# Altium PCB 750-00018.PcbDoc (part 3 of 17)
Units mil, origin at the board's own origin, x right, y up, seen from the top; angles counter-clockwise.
Board outline 7086.64 x 6299.21 mil, 8 copper layers (Top Layer, L2, L3, L4, L5, L6, L7, Bottom Layer), stack 60.6 mil thick; 1356 components, 1054 nets, 4851 pads, 4296 vias.
Unrouted connection lines stored in the file: 12.
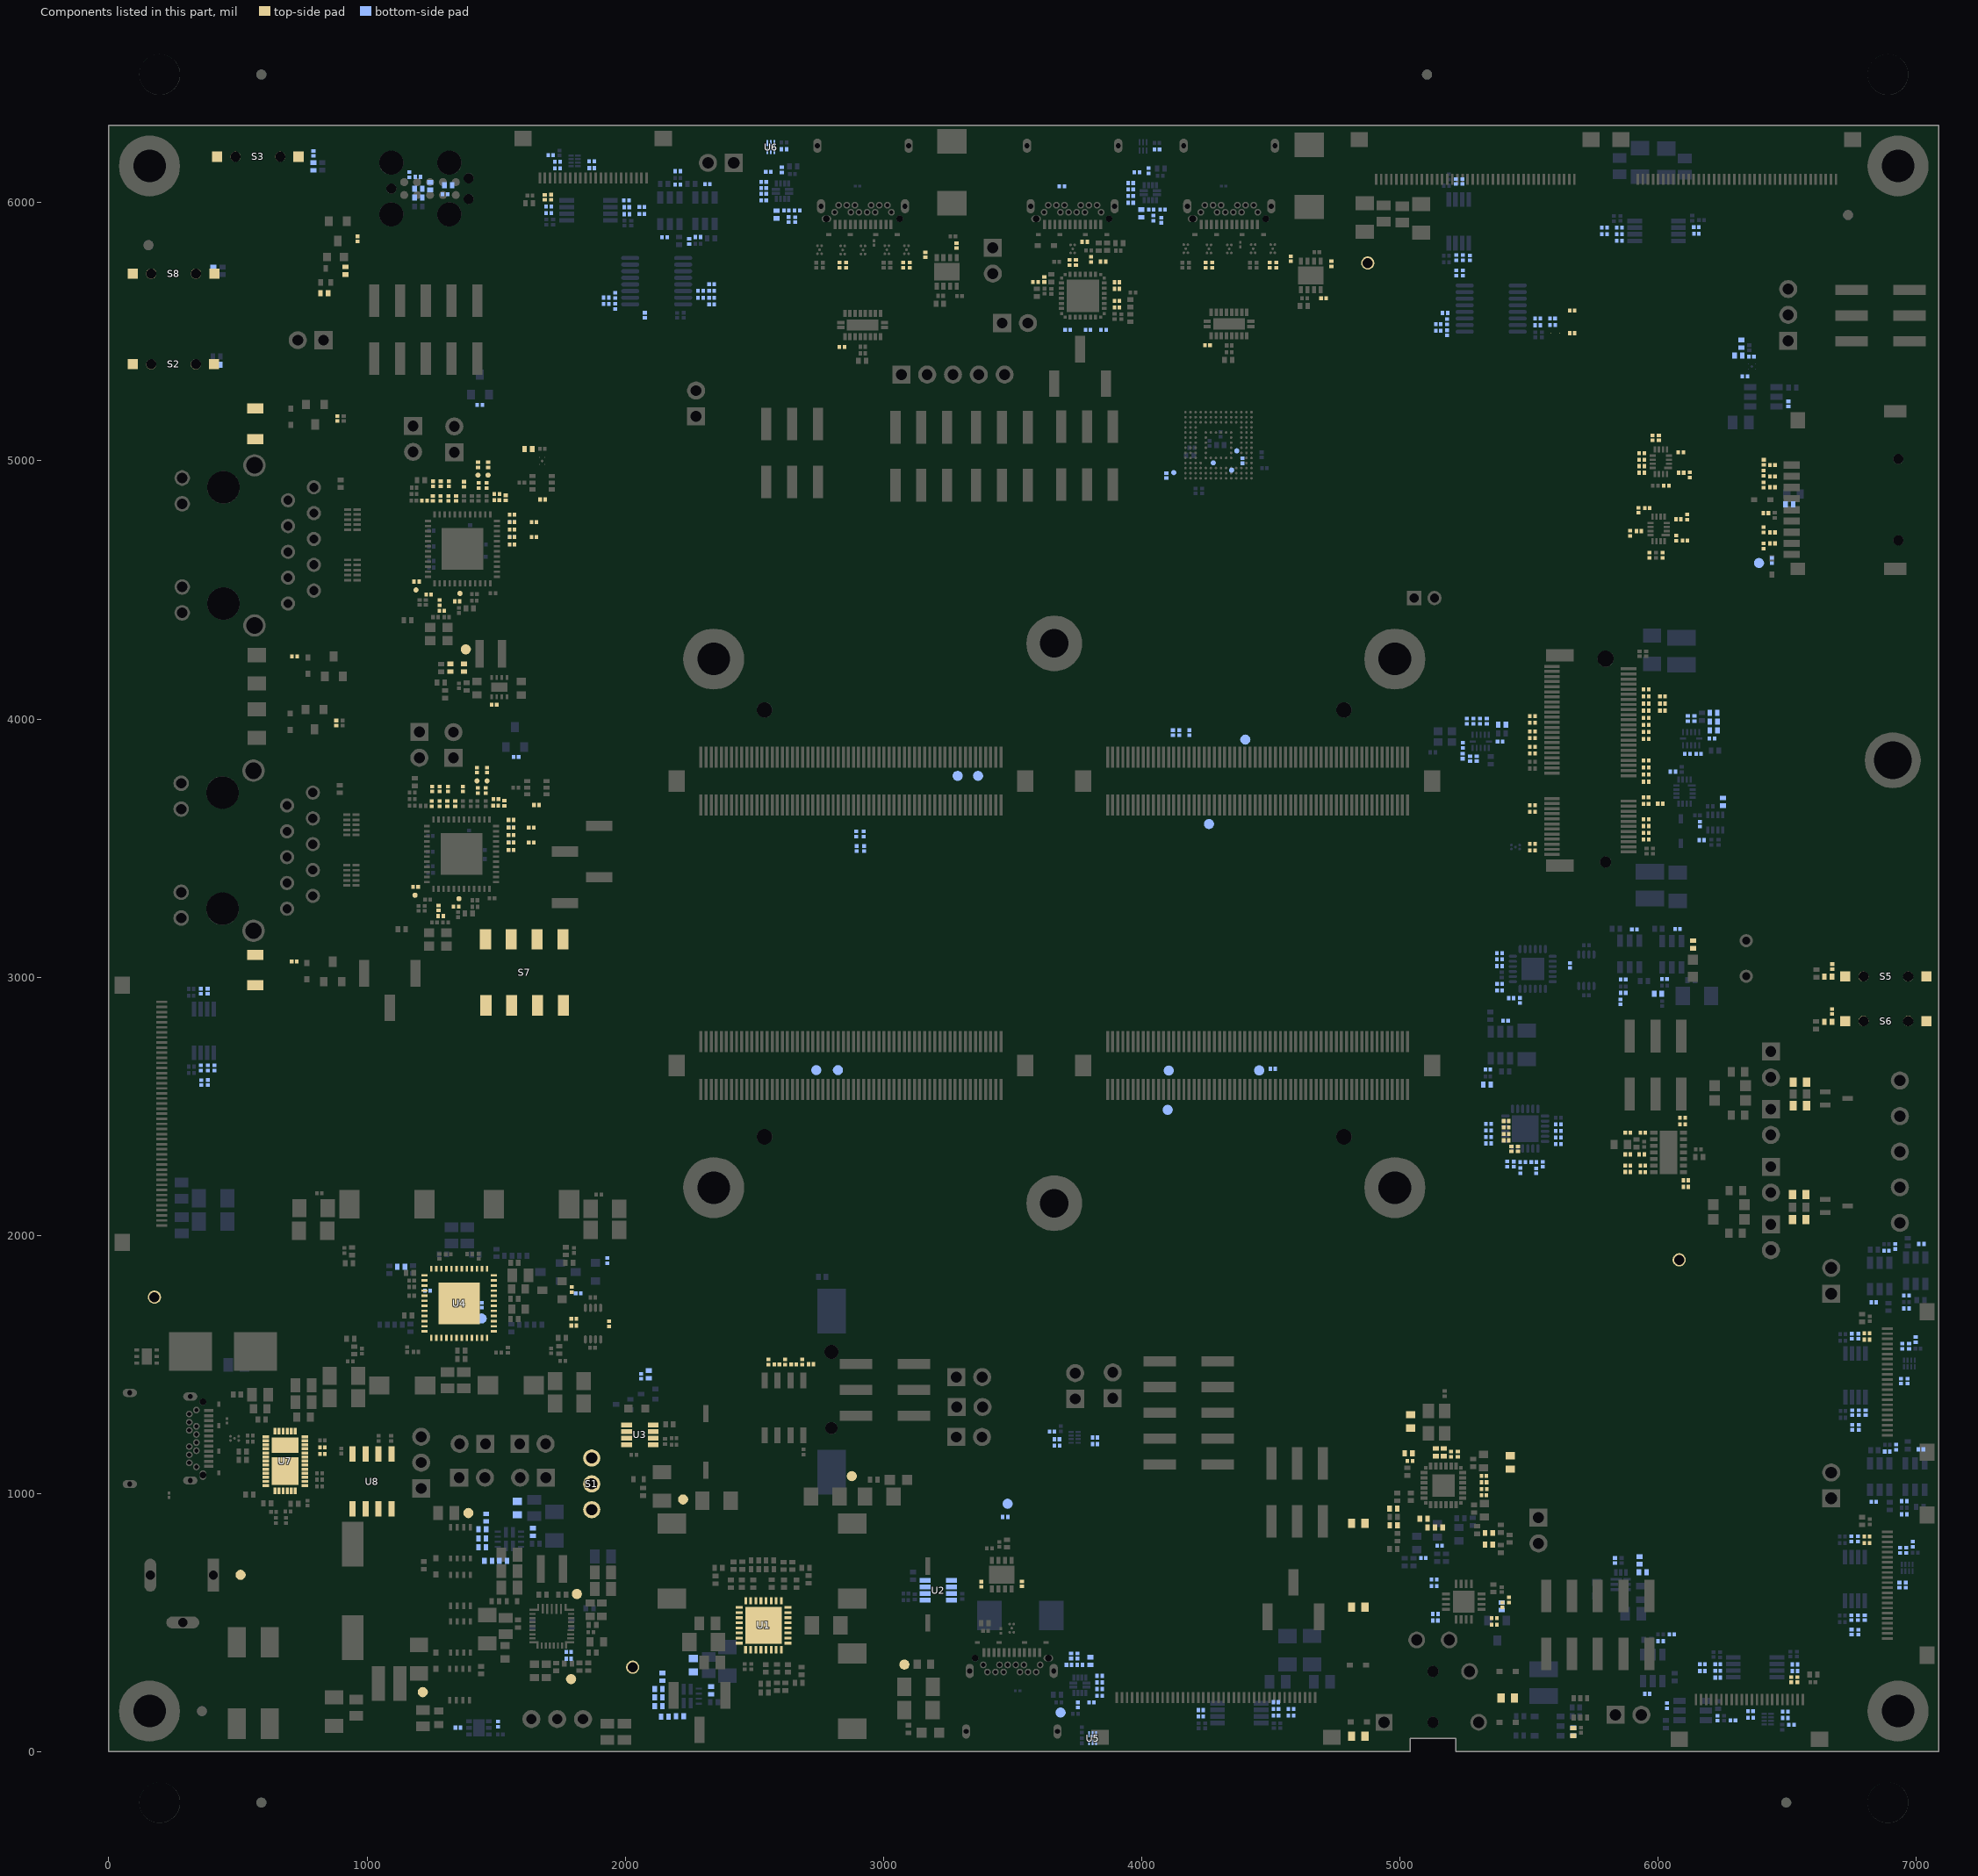
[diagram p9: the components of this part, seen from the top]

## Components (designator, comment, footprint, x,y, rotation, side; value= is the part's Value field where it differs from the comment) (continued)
R78 "0201, 2.2K, 5%" "RES, R0201, Height 0.23mm" 1345.13,3273.14 r0 top value=2.2k
R79 "0201, 2.2K, 5%" "RES, R0201, Height 0.23mm" 1341.29,3671.92 r90 top value=2.2k
R80 "0201, 27 Ohm" "RES, R0201, Height 0.23mm" 1498.34,3664.85 r180 top value=27
R81 "0201, 100 Ohm, 1%" "RES, R0201, Height 0.23mm" 880.75,3984.42 r270 top value=100
R82 "1206, 1M, 5%" "RES, 1206, Height 0.70mm" 567.06,3027.52 r270 top value=1M
R83 "0201, 27 Ohm" "RES, R0201, Height 0.23mm" 1557.78,3492.99 r180 top value=27
R84 "0201, 27 Ohm" "RES, R0201, Height 0.23mm" 1557.78,3521.96 r180 top value=27
R85 "0201, 100 Ohm, 1%" "RES, R0201, Height 0.23mm" 717.9,3061.03 r180 top value=100
R86 "0201, 27 Ohm" "RES, R0201, Height 0.23mm" 1557.78,3550.93 r180 top value=27
R87 "0201, 0 Ohm" "RES, R0201, Height 0.23mm" 1371.42,3728.74 r90 top value=0
R88 "0201, 27 Ohm" "RES, R0201, Height 0.23mm" 1557.78,3579.89 r180 top value=27
R89 "0201, 27 Ohm" "RES, R0201, Height 0.23mm" 1557.78,3608.86 r180 top value=27
R90 "0201, 11k, 1%" "RES, R0201, Height 0.23mm" 1187.88,3349.91 r180 top value=11k
R91 "0201, 0 Ohm" "RES, R0201, Height 0.23mm" 1276.99,3268.29 r270 top value=0
R92 "0201, 1M, 1%" "RES, R0201, Height 0.23mm" 1285.5,3236.84 r0 top value=1M
R93 "0201, 6.04k, 1%" "RES, R0201, Height 0.23mm" 1251.7,3728.74 r270 top value=6.04k
R94 "0201, 11k, 1%" "RES, R0201, Height 0.23mm" 1281.53,3728.74 r270 top value=11k
R95 "0201, 6.04k, 1%" "RES, R0201, Height 0.23mm" 1313.17,3728.74 r270 top value=6.04k
R96 "0201, 6.04k, 1%" "RES, R0201, Height 0.23mm" 1636.09,3579.89 r180 top value=6.04k
R97 "0201, 2.49K, 1%" "RES, R0201, Height 0.23mm" 1636.09,3521.96 r0 top value=2.49k
R98 "0201, 6.04k, 1%" "RES, R0201, Height 0.23mm" 1425.9,3802.07 r270 top value=6.04k
R99 "0201, 6.04k, 1%" "RES, R0201, Height 0.23mm" 1464.72,3802.07 r270 top value=6.04k
R100 "0201, 6.04k, 1%" "RES, R0201, Height 0.23mm" 1498.91,3689.35 r0 top value=6.04k
R101 "0201, 2.49K, 1%" "RES, R0201, Height 0.23mm" 1531.89,3673.64 r90 top value=2.49k
R102 "0201, 2.49K, 1%" "RES, R0201, Height 0.23mm" 1459.11,3722.63 r270 top value=2.49k
R103 "0201, 2.49K, 1%" "RES, R0201, Height 0.23mm" 1428.59,3722.8 r270 top value=2.49k
R104 "0201, 2.49K, 1%" "RES, R0201, Height 0.23mm" 1557.78,3521.96 r180 bottom value=2.49k
R105 "0201, 2.49K, 1%" "RES, R0201, Height 0.23mm" 1557.78,3579.89 r180 bottom value=2.49k
R106 "0201, 2.49K, 1%" "RES, R0201, Height 0.23mm" 1310.75,3671.99 r90 top value=2.49k
R107 "0201, 2.49K, 1%" "RES, R0201, Height 0.23mm" 1280.84,3671.99 r90 top value=2.49k
R108 "0201, 2.49K, 1%" "RES, R0201, Height 0.23mm" 1250.74,3671.99 r90 top value=2.49k
R109 "0201, 0 Ohm" "RES, R0201, Height 0.23mm" 1238.63,4482.59 r0 top value=0
R110 "0201, 0 Ohm" "RES, R0201, Height 0.23mm" 1222.46,4845.96 r0 top value=0
R111 "0201, 2.2K, 5%" "RES, R0201, Height 0.23mm" 1349.07,4455.46 r0 top value=2.2k
R112 "0201, 2.2K, 5%" "RES, R0201, Height 0.23mm" 1344.76,4854.47 r90 top value=2.2k
R113 "0201, 27 Ohm" "RES, R0201, Height 0.23mm" 1502.28,4847.17 r180 top value=27
R114 "0201, 100 Ohm, 1%" "RES, R0201, Height 0.23mm" 884.69,5163.92 r270 top value=100
R115 "1206, 1M, 5%" "RES, 1206, Height 0.70mm" 567.06,5143.47 r90 top value=1M
R116 "0201, 27 Ohm" "RES, R0201, Height 0.23mm" 1561.72,4675.31 r180 top value=27
R117 "0201, 27 Ohm" "RES, R0201, Height 0.23mm" 1561.72,4704.27 r180 top value=27
R118 "0201, 100 Ohm, 1%" "RES, R0201, Height 0.23mm" 718.94,4242.61 r180 top value=100
R119 "0201, 27 Ohm" "RES, R0201, Height 0.23mm" 1561.72,4733.24 r180 top value=27
R120 "0201, 0 Ohm" "RES, R0201, Height 0.23mm" 1375.56,4909.05 r90 top value=0
R121 "0201, 27 Ohm" "RES, R0201, Height 0.23mm" 1561.72,4762.21 r180 top value=27
R122 "0201, 27 Ohm" "RES, R0201, Height 0.23mm" 1561.72,4791.18 r180 top value=27
R123 "0201, 11k, 1%" "RES, R0201, Height 0.23mm" 1191.83,4532.22 r180 top value=11k
R124 "0201, 0 Ohm" "RES, R0201, Height 0.23mm" 1280.93,4450.61 r270 top value=0
R125 "0201, 1M, 1%" "RES, R0201, Height 0.23mm" 1289.44,4419.16 r0 top value=1M
R126 "0201, 6.04k, 1%" "RES, R0201, Height 0.23mm" 1255.64,4910.93 r270 top value=6.04k
R127 "0201, 11k, 1%" "RES, R0201, Height 0.23mm" 1285.47,4910.93 r270 top value=11k
R128 "0201, 6.04k, 1%" "RES, R0201, Height 0.23mm" 1316.62,4910.93 r270 top value=6.04k
R129 "0201, 6.04k, 1%" "RES, R0201, Height 0.23mm" 1646.32,4762.21 r180 top value=6.04k
R130 "0201, 11k, 1%" "RES, R0201, Height 0.23mm" 1646.32,4705.15 r180 top value=11k
R131 "0201, 6.04k, 1%" "RES, R0201, Height 0.23mm" 1429.85,4984.39 r270 top value=6.04k
R132 "0201, 6.04k, 1%" "RES, R0201, Height 0.23mm" 1468.66,4984.39 r270 top value=6.04k
R133 "0201, 6.04k, 1%" "RES, R0201, Height 0.23mm" 1502.85,4871.67 r0 top value=6.04k
R134 "0201, 2.49K, 1%" "RES, R0201, Height 0.23mm" 1536.93,4856.33 r90 top value=2.49k
R135 "0201, 2.49K, 1%" "RES, R0201, Height 0.23mm" 1463.05,4904.7 r270 top value=2.49k
R136 "0201, 2.49K, 1%" "RES, R0201, Height 0.23mm" 1432.53,4904.87 r270 top value=2.49k
R137 "0201, 2.49K, 1%" "RES, R0201, Height 0.23mm" 1561.72,4704.27 r180 bottom value=2.49k
R138 "0201, 2.49K, 1%" "RES, R0201, Height 0.23mm" 1561.72,4762.21 r180 bottom value=2.49k
R139 "0201, 2.49K, 1%" "RES, R0201, Height 0.23mm" 1314.7,4854.3 r90 top value=2.49k
R140 "0201, 2.49K, 1%" "RES, R0201, Height 0.23mm" 1284.79,4854.3 r90 top value=2.49k
R141 "0201, 2.49K, 1%" "RES, R0201, Height 0.23mm" 1254.68,4854.3 r90 top value=2.49k
R142 "0201, 100k, 5%" "RES, R0201, Height 0.23mm" 3536.21,650.36 r90 top value=100k
R143 "0201, 10k, 5%" "RES, R0201, Height 0.23mm" 1444.01,1729.74 r90 bottom value=10k
R144 "0402, 0 Ohm" "RES, R0402, RF" 5091.73,902.15 r0 top value=0
R145 "0201, 0 Ohm" "RES, R0201, Height 0.23mm" 2614.54,6206.95 r180 bottom value=0
R146 "0201, 0 Ohm" "RES, R0201, Height 0.23mm" 4059.28,6205.78 r180 bottom value=0
R147 "0201, 1.0k, 5%" "RES, R0201, Height 0.23mm" 2633,5934.14 r270 bottom value=1.0k
R148 "0402, 909k, 1%" "RES, R0402, RF" 2585.9,5953.71 r270 bottom value=909k
R149 "0201, 47k, 1%" "RES, R0201, Height 0.23mm" 1817.86,1775.2 r0 bottom value=47k
R150 "0201, 200k, 1%" "RES, R0201, Height 0.23mm" 2536,6008.77 r180 bottom value=200k
R151 "0201, 200k, 1%" "RES, R0201, Height 0.23mm" 2553.91,6118.73 r180 bottom value=200k
R152 "0201, 10k, 5%" "RES, R0201, Height 0.23mm" 2623.88,5969.02 r0 bottom value=10k
R153 "0201, 200k, 1%" "RES, R0201, Height 0.23mm" 2536,6033.9 r180 bottom value=200k
R154 "0201, 200k, 1%" "RES, R0201, Height 0.23mm" 2536,6080.37 r180 bottom value=200k
R155 "0201, 1.0k, 5%" "RES, R0201, Height 0.23mm" 2665.88,5969.08 r180 bottom value=1.0k
R156 "0201, 1.0k, 5%" "RES, R0201, Height 0.23mm" 2536,6056.5 r0 bottom value=1.0k
R157 "0201, 10k, 5%" "RES, R0201, Height 0.23mm" 2605.96,6127.17 r90 bottom value=10k
R158 "0201, 100k, 5%" "RES, R0201, Height 0.23mm" 3162.21,5797.67 r90 top value=100k
R159 "0201, 10k, 5%" "RES, R0201, Height 0.23mm" 2839.47,5441.38 r0 top value=10k
R160 "0201, 10k, 5%" "RES, R0201, Height 0.23mm" 6016.99,4087.9 r180 top value=10k
R161 "0201, 10k, 5%" "RES, R0201, Height 0.23mm" 1930.77,1902.17 r270 bottom value=10k
R162 "0201, 1.0k, 5%" "RES, R0201, Height 0.23mm" 4045.78,5939.69 r270 bottom value=1.0k
R163 "0402, 909k, 1%" "RES, R0402, RF" 3999.01,5957.89 r270 bottom value=909k
R164 "0201, 10k, 5%" "RES, R0201, Height 0.23mm" 4075.93,5931.94 r270 bottom value=10k
R165 "0201, 200k, 1%" "RES, R0201, Height 0.23mm" 3957.18,5999.37 r180 bottom value=200k
R166 "0201, 200k, 1%" "RES, R0201, Height 0.23mm" 3981.83,6117.74 r180 bottom value=200k
R167 "0201, 10k, 5%" "RES, R0201, Height 0.23mm" 4036.83,5973.55 r0 bottom value=10k
R168 "0201, 200k, 1%" "RES, R0201, Height 0.23mm" 3957.18,6025.38 r180 bottom value=200k
R169 "0201, 200k, 1%" "RES, R0201, Height 0.23mm" 3957.19,6075.99 r180 bottom value=200k
R170 "0201, 1.0k, 5%" "RES, R0201, Height 0.23mm" 4080.78,5973.24 r180 bottom value=1.0k
R171 "0201, 1.0k, 5%" "RES, R0201, Height 0.23mm" 3957.19,6050.85 r0 bottom value=1.0k
R172 "0201, 10k, 5%" "RES, R0201, Height 0.23mm" 4026.16,6123.19 r90 bottom value=10k
R173 "0201, 100k, 5%" "RES, R0201, Height 0.23mm" 4576.9,5782.77 r90 top value=100k
R174 "0201, 10k, 5%" "RES, R0201, Height 0.23mm" 4254.62,5448.08 r0 top value=10k
R175 "0201, 10k, 5%" "RES, R0201, Height 0.23mm" 4704.5,5630.07 r180 top value=10k
R176 "0402, 0 Ohm" "RES, R0402, RF" 417.35,5371.37 r180 bottom value=0
R177 "0603, 0 Ohm" "RES, R0603, RF" 5417.44,207.97 r180 top value=0
R178 "0603, 0 Ohm" "RES, R0603, RF" 4838.42,559.47 r0 top value=0
R179 "0603, 0 Ohm" "RES, R0603, RF" 5427.17,1120.59 r270 top value=0
R180 "0603, 0 Ohm" "RES, R0603, RF" 4839.09,884.98 r0 top value=0
R181 "0603, 0 Ohm" "RES, R0603, RF" 5041.54,1279.36 r270 top value=0
R182 "0603, 0 Ohm" "RES, R0603, RF" 4839,60.01 r0 top value=0
R183 "0201, 27 Ohm" "RES, R0201, Height 0.23mm" 5326.01,1017.94 r180 top value=27
R184 "0201, 27 Ohm" "RES, R0201, Height 0.23mm" 5325.61,993.06 r180 top value=27
R185 "0201, 27 Ohm" "RES, R0201, Height 0.23mm" 5325.2,1068.5 r180 top value=27
R186 "0201, 27 Ohm" "RES, R0201, Height 0.23mm" 5325.81,1043.83 r180 top value=27
R187 "0201, 10k, 5%" "RES, R0201, Height 0.23mm" 5153.82,797.72 r0 bottom value=10k
R188 "0402, 330k, 1%" "RES, R0402, RF" 5393.56,563.42 r90 bottom value=330k
R189 "0201, 0 Ohm" "RES, R0201, Height 0.23mm" 5198.09,1152.54 r270 top value=0
R190 "0201, 0 Ohm" "RES, R0201, Height 0.23mm" 5224,1152.24 r270 top value=0
R191 "0201, 10k, 5%" "RES, R0201, Height 0.23mm" 5091,750.96 r180 bottom value=10k
R192 "0201, 0 Ohm" "RES, R0201, Height 0.23mm" 5132.44,641.5 r0 bottom value=0
R193 "0402, 68.1k, 1%" "RES, R0402, RF" 1445.97,792.73 r0 bottom value=68.1k
R194 "0201, 0 Ohm" "RES, R0201, Height 0.23mm" 5422.49,588.33 r270 top value=0
R195 "0201, 0 Ohm" "RES, R0201, Height 0.23mm" 5137.15,508.39 r0 bottom value=0
R196 "0201, 4.7k, 5%" "RES, R0201, Height 0.23mm" 5132.22,667.17 r0 bottom value=4.7k
R197 "0201, 4.7k, 5%" "RES, R0201, Height 0.23mm" 5397.35,568.65 r90 top value=4.7k
R198 "0201, 100k, 5%" "RES, R0201, Height 0.23mm" 5137.2,533.64 r0 bottom value=100k
R199 "0402, 4.99k, 1%" "RES, R0402, RF" 1445.97,826.9 r180 bottom value=4.99k
R200 "0402, 68.1k, 1%" "RES, R0402, RF" 2129.04,176.74 r0 bottom value=68.1k
R201 "0201, 0 Ohm" "RES, R0201, Height 0.23mm" 5365.72,492.02 r180 top value=0
R202 "0201, 100k, 5%" "RES, R0201, Height 0.23mm" 5365.71,517.41 r0 top value=100k
R203 "0402, 0 Ohm" "RES, R0402, RF" 5672.06,76.79 r270 top value=0
R204 "0402, 2.2k, 5%" "RES, R0402, RF" 4975.68,876.38 r180 top value=2.2k
R205 "0402, 47k, 1%" "RES, R0402, RF" 4974.94,942.22 r180 top value=47k
R206 "0402, 100k, 1%" "RES, R0402, RF" 5671.34,77.78 r270 bottom value=100k
R207 "0402, 0 Ohm" "RES, R0402, RF" 5344.65,803.14 r0 top value=0
R208 "0402, 0 Ohm" "RES, R0402, RF" 5344.35,847.44 r0 top value=0
R209 "0201, 0 Ohm" "RES, R0201, Height 0.23mm" 5613.69,2404.55 r180 bottom value=0
R210 "0201, 0 Ohm" "RES, R0201, Height 0.23mm" 827.26,1179.45 r0 top value=0
R211 "0201, 2.2K, 5%" "RES, R0201, Height 0.23mm" 4578.47,165.88 r180 bottom value=2.2k
R212 "0201, 2.2K, 5%" "RES, R0201, Height 0.23mm" 4578.47,140.49 r180 bottom value=2.2k
R213 "0201, 2.2K, 5%" "RES, R0201, Height 0.23mm" 5244.31,5727.26 r90 bottom value=2.2k
R214 "0201, 2.2K, 5%" "RES, R0201, Height 0.23mm" 5218.49,5727.26 r90 bottom value=2.2k
R215 "0201, 2.2K, 5%" "RES, R0201, Height 0.23mm" 5792.26,5877.28 r0 bottom value=2.2k
R216 "0201, 2.2K, 5%" "RES, R0201, Height 0.23mm" 5792.39,5903.06 r0 bottom value=2.2k
R217 "0201, 2.2K, 5%" "RES, R0201, Height 0.23mm" 383.39,2591.87 r90 bottom value=2.2k
R218 "0201, 2.2K, 5%" "RES, R0201, Height 0.23mm" 357.58,2591.62 r90 bottom value=2.2k
R219 "0201, 2.2K, 5%" "RES, R0201, Height 0.23mm" 5590.88,5551.51 r180 bottom value=2.2k
R220 "0201, 2.2K, 5%" "RES, R0201, Height 0.23mm" 5591.11,5525.46 r180 bottom value=2.2k
R221 "0201, 10k, 5%" "RES, R0201, Height 0.23mm" 2924.61,3498.16 r270 bottom value=10k
R222 "0402, 0 Ohm" "RES, R0402, RF" 6214.75,3956.24 r0 bottom value=0
R223 "0402, 0 Ohm" "RES, R0402, RF" 6214.84,3990.2 r0 bottom value=0
R224 "0402, 0 Ohm" "RES, R0402, RF" 5395.31,3978.41 r0 bottom value=0
R225 "0402, 0 Ohm" "RES, R0402, RF" 6214.52,4023.88 r0 bottom value=0
R226 "0201, 49.9k, 1%" "RES, R0201, Height 0.23mm" 6156.8,3865.05 r180 bottom value=49.9k
R227 "0201, 49.9k, 1%" "RES, R0201, Height 0.23mm" 6113.43,3865.05 r0 bottom value=49.9k
R228 "0201, 10k, 5%" "RES, R0201, Height 0.23mm" 5387.98,3913 r0 bottom value=10k
R229 "0201, 10k, 5%" "RES, R0201, Height 0.23mm" 6208.37,3924.64 r0 bottom value=10k
R230 "0201, 10k, 5%" "RES, R0201, Height 0.23mm" 1492.29,4055.55 r180 top value=10k
R231 "0402, 66.5k, 1%" "RES, R0402, RF" 1322.8,4198.42 r90 top value=66.5k
R232 "0201, 49.9k, 1%" "RES, R0201, Height 0.23mm" 6162.26,3592.82 r90 bottom value=49.9k
R233 "0402, 10k, 1%" "RES, R0402, RF" 6251.33,3678.99 r270 bottom value=10.0k
R234 "0201, 0 Ohm" "RES, R0201, Height 0.23mm" 5533.72,5551.18 r180 bottom value=0
R235 "0201, 10k, 5%" "RES, R0201, Height 0.23mm" 2895.68,3498.14 r270 bottom value=10k
R236 "0201, 0 Ohm" "RES, R0201, Height 0.23mm" 5953.3,4114.79 r180 top value=0
R237 "0201, 0 Ohm" "RES, R0201, Height 0.23mm" 6075.1,3186.34 r0 bottom value=0
R238 "0201, 0 Ohm" "RES, R0201, Height 0.23mm" 5953.3,4087.27 r180 top value=0
R239 "0402, 2.2k, 5%" "RES, R0402, RF" 6135.05,3126.64 r90 top value=2.2k
R240 "0201, 0 Ohm" "RES, R0201, Height 0.23mm" 5953.3,4059.76 r180 top value=0
R241 "0201, 0 Ohm" "RES, R0201, Height 0.23mm" 5953.3,4032.25 r180 top value=0
R242 "0201, 0 Ohm" "RES, R0201, Height 0.23mm" 5953.3,4004.73 r180 top value=0
R243 "0201, 0 Ohm" "RES, R0201, Height 0.23mm" 5513.08,4010.79 r180 top value=0
R244 "0402, 0 Ohm" "RES, R0402, RF" 5999.5,2936.63 r0 bottom value=0
R245 "0201, 0 Ohm" "RES, R0201, Height 0.23mm" 5953.3,3977.22 r180 top value=0
R246 "0201, 0 Ohm" "RES, R0201, Height 0.23mm" 5513.08,3985.14 r180 top value=0
R247 "0201, 0 Ohm" "RES, R0201, Height 0.23mm" 5953.3,3949.71 r180 top value=0
R248 "0201, 49.9k, 1%" "RES, R0201, Height 0.23mm" 6024.56,2992.64 r180 bottom value=49.9k
R249 "0201, 0 Ohm" "RES, R0201, Height 0.23mm" 5953.3,3922.19 r180 top value=0
R250 "0201, 0 Ohm" "RES, R0201, Height 0.23mm" 5513.08,3951.24 r180 top value=0
R251 "0201, 0 Ohm" "RES, R0201, Height 0.23mm" 5513.08,3925.8 r180 top value=0
R252 "0402, 4.99k, 1%" "RES, R0402, RF" 2128.88,210.43 r180 bottom value=4.99k
R253 "0402, 30k, 1%" "RES, R0402, RF" 1641.59,850.96 r90 bottom value=30k
R254 "0201, 0 Ohm" "RES, R0201, Height 0.23mm" 5953.3,3839.65 r180 top value=0
R255 "0201, 0 Ohm" "RES, R0201, Height 0.23mm" 5533.51,5525.22 r180 bottom value=0
R256 "0201, 1.0k, 5%" "RES, R0201, Height 0.23mm" 5953.3,3812.14 r180 top value=1.0k
R257 "0201, 1.0k, 5%" "RES, R0201, Height 0.23mm" 5953.3,3784.63 r180 top value=1.0k
R258 "0201, 1.0k, 5%" "RES, R0201, Height 0.23mm" 5953.3,3757.11 r180 top value=1.0k
R259 "0201, 10k, 5%" "RES, R0201, Height 0.23mm" 6008.45,3672 r180 top value=10k
R260 "0402, 27.4k, 1%" "RES, R0402, RF" 1527.02,738.76 r180 bottom value=27.4k
R261 "0201, 1.0k, 5%" "RES, R0201, Height 0.23mm" 5953.1,3696.84 r180 top value=1.0k
R262 "0201, 10k, 5%" "RES, R0201, Height 0.23mm" 4507.57,2645.01 r0 bottom value=10k
R263 "0201, 0 Ohm" "RES, R0201, Height 0.23mm" 5513.08,3666.42 r180 top value=0
R264 "0201, 0 Ohm" "RES, R0201, Height 0.23mm" 5953.1,3670.74 r180 top value=0
R265 "0201, 0 Ohm" "RES, R0201, Height 0.23mm" 5953.38,3611.33 r180 top value=0
R266 "0201, 0 Ohm" "RES, R0201, Height 0.23mm" 5953.3,3585.33 r180 top value=0
R267 "0201, 0 Ohm" "RES, R0201, Height 0.23mm" 5953.2,3559.47 r180 top value=0
R268 "0201, 0 Ohm" "RES, R0201, Height 0.23mm" 5953.4,3533.91 r180 top value=0
R269 "0201, 0 Ohm" "RES, R0201, Height 0.23mm" 5513.08,3516.77 r180 top value=0
R270 "0201, 0 Ohm" "RES, R0201, Height 0.23mm" 5513.08,3491.09 r180 top value=0
R271 "0402, 30k, 1%" "RES, R0402, RF" 2331.78,237.37 r90 bottom value=30k
R272 "0402, 27.4k, 1%" "RES, R0402, RF" 2211.7,136.92 r180 bottom value=27.4k
R273 "0201, 0 Ohm" "RES, R0201, Height 0.23mm" 827.26,1153.58 r0 top value=0
R274 "0402, 0 Ohm" "RES, R0402, RF" 5151.06,867.94 r0 top value=0
R275 "0603, 60.4, 1%" "RES, R0603, RF" 6548.73,2593.76 r180 top value=60.4
R276 "0402, 0 Ohm" "RES, R0402, RF" 5121.54,867.94 r180 top value=0
R277 "0603, 60.4, 1%" "RES, R0603, RF" 6548.73,2502.5 r0 top value=60.4
R278 "0201, 0 Ohm" "RES, R0201, Height 0.23mm" 1780.94,386.89 r0 bottom value=0
R279 "0201, 4.7k, 5%" "RES, R0201, Height 0.23mm" 6094.87,2455.67 r180 top value=4.7k
R280 "0201, 0 Ohm" "RES, R0201, Height 0.23mm" 1780.85,360.59 r0 bottom value=0
R281 "0201, 0 Ohm" "RES, R0201, Height 0.23mm" 5513.08,3892.69 r180 top value=0
R282 "0603, 60.4, 1%" "RES, R0603, RF" 6546.49,2158.23 r180 top value=60.4
R283 "0201, 0 Ohm" "RES, R0201, Height 0.23mm" 5513.08,3867.07 r180 top value=0
R284 "0603, 60.4, 1%" "RES, R0603, RF" 6546.49,2060.58 r0 top value=60.4
R285 "0201, 200k, 1%" "RES, R0201, Height 0.23mm" 6986.66,804.03 r90 bottom value=200k
R286 "0201, 4.7k, 5%" "RES, R0201, Height 0.23mm" 6107.37,2187.79 r180 top value=4.7k
R287 "0201, 10k, 5%" "RES, R0201, Height 0.23mm" 3713.48,5506.89 r180 bottom value=10k
R288 "0201, 4.7k, 5%" "RES, R0201, Height 0.23mm" 3588.51,5692.93 r0 top value=4.7k
R289 "0201, 4.7k, 5%" "RES, R0201, Height 0.23mm" 6016.99,4059.62 r180 top value=4.7k
R290 "0201, 4.7k, 5%" "RES, R0201, Height 0.23mm" 3904.18,5691.39 r180 top value=4.7k
R291 "0201, 10k, 5%" "RES, R0201, Height 0.23mm" 3622.71,5702.23 r90 top value=10k
R292 "0201, 10k, 5%" "RES, R0201, Height 0.23mm" 3850.77,5771.36 r0 top value=10k
R293 "0201, 4.7k, 5%" "RES, R0201, Height 0.23mm" 3904.18,5665.95 r180 top value=4.7k
R294 "0201, 4.7k, 5%" "RES, R0201, Height 0.23mm" 3904.21,5619.25 r180 top value=4.7k
R295 "0201, 10k, 5%" "RES, R0201, Height 0.23mm" 3803.97,5780.06 r90 top value=10k
R296 "0201, 1.0k, 5%" "RES, R0201, Height 0.23mm" 3904.21,5593.77 r0 top value=1.0k
R297 "0201, 1.0k, 5%" "RES, R0201, Height 0.23mm" 3792.16,5506.89 r180 bottom value=1.0k
R298 "0201, 0 Ohm" "RES, R0201, Height 0.23mm" 3852.35,5506.89 r180 bottom value=0
R299 "0201, 4.7k, 5%" "RES, R0201, Height 0.23mm" 6016.99,4032.19 r180 top value=4.7k
R300 "0201, 0 Ohm" "RES, R0201, Height 0.23mm" 5297.42,3846.08 r90 bottom value=0
R301 "0402, 100k, 1%" "RES, R0402, RF" 1375.56,4198.42 r90 top value=100k
R302 "0201, 0 Ohm" "RES, R0201, Height 0.23mm" 5613.69,2429.99 r180 bottom value=0
R303 "0201, 10k, 5%" "RES, R0201, Height 0.23mm" 5553.28,2275.19 r270 bottom value=10k
R304 "0201, 0 Ohm" "RES, R0201, Height 0.23mm" 6440.88,4614.13 r90 bottom value=0
R305 "0201, 0 Ohm" "RES, R0201, Height 0.23mm" 6017.19,4633.99 r90 top value=0
R306 "0201, 0 Ohm" "RES, R0201, Height 0.23mm" 6070.24,4700.85 r270 top value=0
R307 "0201, 0 Ohm" "RES, R0201, Height 0.23mm" 6078.7,4773.74 r0 top value=0
R308 "0201, 0 Ohm" "RES, R0201, Height 0.23mm" 5957.64,4817.39 r180 top value=0
R309 "0201, 0 Ohm" "RES, R0201, Height 0.23mm" 6442.61,4897.47 r0 top value=0
R310 "0201, 0 Ohm" "RES, R0201, Height 0.23mm" 5925.37,4727.64 r180 top value=0
R311 "0201, 0 Ohm" "RES, R0201, Height 0.23mm" 6417.24,4797.49 r0 top value=0
R312 "0201, 0 Ohm" "RES, R0201, Height 0.23mm" 6089.06,4953.85 r0 top value=0
R313 "0201, 0 Ohm" "RES, R0201, Height 0.23mm" 6442.61,4722.86 r0 top value=0
R314 "0201, 0 Ohm" "RES, R0201, Height 0.23mm" 6088,5032.9 r0 top value=0
R315 "0201, 0 Ohm" "RES, R0201, Height 0.23mm" 6442.61,4679.99 r0 top value=0
R316 "0201, 0 Ohm" "RES, R0201, Height 0.23mm" 6442.8,4983.49 r0 top value=0
R317 "0201, 0 Ohm" "RES, R0201, Height 0.23mm" 6442.61,4939.89 r0 top value=0
R318 "0402, 0 Ohm" "RES, R0402, RF" 6508.01,4831.19 r180 bottom value=0
R319 "0201, 0 Ohm" "RES, R0201, Height 0.23mm" 6504.35,5220.13 r270 bottom value=0
R320 "0402, 10k, 1%" "RES, R0402, RF" 1198.8,6019.29 r0 bottom value=10.0k
R321 "0402, 10k, 1%" "RES, R0402, RF" 1198.8,6053.95 r0 bottom value=10.0k
R322 "0201, 49.9k, 1%" "RES, R0201, Height 0.23mm" 1197.16,6099.9 r180 bottom value=49.9k
R323 "0402, 10k, 1%" "RES, R0402, RF" 1243.79,6063.88 r90 bottom value=10.0k
R324 "0402, 10k, 1%" "RES, R0402, RF" 1314.58,6067.47 r180 bottom value=10.0k
R325 "0201, 0 Ohm" "RES, R0201, Height 0.23mm" 3720.05,5768 r270 top value=0
R326 "0201, 174k, 1%" "RES, R0201, Height 0.23mm" 3378.5,648.92 r270 top value=174k
R327 "0201, 10k, 5%" "RES, R0201, Height 0.23mm" 2658.41,5933.97 r270 bottom value=10k
R328 "0201, 0 Ohm" "RES, R0201, Height 0.23mm" 5386.13,2973.64 r0 bottom value=0
R329 "0201, 0 Ohm" "RES, R0201, Height 0.23mm" 5386.13,2948.6 r0 bottom value=0
R330 "0201, 10k, 5%" "RES, R0201, Height 0.23mm" 5386.09,3043.24 r180 bottom value=10k
R331 "0201, 10k, 5%" "RES, R0201, Height 0.23mm" 1656.32,3666.72 r180 top value=10k
R332 "0201, 0 Ohm" "RES, R0201, Height 0.23mm" 5386.09,3069.74 r180 bottom value=0
R333 "0201, 0 Ohm" "RES, R0201, Height 0.23mm" 5464.78,2909.9 r270 bottom value=0
R334 "0201, 0 Ohm" "RES, R0201, Height 0.23mm" 5430.96,2918.88 r0 bottom value=0
R335 "0201, 0 Ohm" "RES, R0201, Height 0.23mm" 5386.09,3093.58 r0 bottom value=0
R336 "0201, 0 Ohm" "RES, R0201, Height 0.23mm" 3076.28,5757.57 r90 top value=0
R337 "0201, 0 Ohm" "RES, R0201, Height 0.23mm" 3101.84,5757.57 r90 top value=0
R338 "0201, 100k, 1%" "RES, R0201, Height 0.23mm" 3283.04,5833.81 r270 top value=100k
R339 "0201, 0 Ohm" "RES, R0201, Height 0.23mm" 2829.95,5757.57 r270 top value=0
R340 "0201, 0 Ohm" "RES, R0201, Height 0.23mm" 2855.1,5757.57 r270 top value=0
R341 "0201, 0 Ohm" "RES, R0201, Height 0.23mm" 4495.34,5757.57 r90 top value=0
R342 "0201, 0 Ohm" "RES, R0201, Height 0.23mm" 4520.89,5757.57 r90 top value=0
R343 "0201, 100k, 1%" "RES, R0201, Height 0.23mm" 4734.47,5763.35 r90 top value=100k
R344 "0201, 0 Ohm" "RES, R0201, Height 0.23mm" 4247.67,5757.57 r270 top value=0
R345 "0201, 0 Ohm" "RES, R0201, Height 0.23mm" 4273.03,5757.57 r270 top value=0
R346 "0402, 22.1k, 1%" "RES, R0402, RF" 5033.24,1156.55 r180 top value=22.1k
R347 "0201, 4.7k, 5%" "RES, R0201, Height 0.23mm" 5038.75,1126.3 r0 top value=4.7k
R348 "0201, 10k, 5%" "RES, R0201, Height 0.23mm" 5174.98,5572.68 r180 bottom value=10k
R349 "0201, 10k, 5%" "RES, R0201, Height 0.23mm" 4519.41,191.79 r0 bottom value=10k
R350 "0201, 0 Ohm" "RES, R0201, Height 0.23mm" 5908.19,3184.78 r0 bottom value=0
R351 "0201, 0 Ohm" "RES, R0201, Height 0.23mm" 5243.57,3898.13 r270 bottom value=0
R352 "0201, 10k, 5%" "RES, R0201, Height 0.23mm" 6168.61,3531.08 r180 bottom value=10k
R353 "0201, 200k, 1%" "RES, R0201, Height 0.23mm" 1711.31,6183.79 r180 bottom value=200k
R354 "0201, 4.7k, 5%" "RES, R0201, Height 0.23mm" 5882.55,2397.49 r180 top value=4.7k
R355 "0201, 0 Ohm" "RES, R0201, Height 0.23mm" 6094.77,2430.09 r0 top value=0
R356 "0201, 4.7k, 5%" "RES, R0201, Height 0.23mm" 5882.55,2313.8 r180 top value=4.7k
R357 "0201, 0 Ohm" "RES, R0201, Height 0.23mm" 5940.66,2397.48 r180 top value=0
R358 "0201, 0 Ohm" "RES, R0201, Height 0.23mm" 5936.87,2313.8 r180 top value=0
R359 "0201, 10k, 5%" "RES, R0201, Height 0.23mm" 6961.41,780.3 r90 bottom value=10k
R360 "0201, 10k, 5%" "RES, R0201, Height 0.23mm" 6936.52,780.14 r90 bottom value=10k
R361 "0201, 4.7k, 5%" "RES, R0201, Height 0.23mm" 5882.55,2245.76 r0 top value=4.7k
R362 "0201, 0 Ohm" "RES, R0201, Height 0.23mm" 6107.44,2213.3 r0 top value=0
R363 "0201, 4.7k, 5%" "RES, R0201, Height 0.23mm" 5882.55,2270.85 r0 top value=4.7k
R364 "0201, 0 Ohm" "RES, R0201, Height 0.23mm" 5940.66,2270.91 r180 top value=0
R365 "0201, 0 Ohm" "RES, R0201, Height 0.23mm" 5940.66,2245.35 r180 top value=0
R366 "0201, 49.9k, 1%" "RES, R0201, Height 0.23mm" 962.64,5859.42 r270 top value=49.9k
R367 "0201, 0 Ohm" "RES, R0201, Height 0.23mm" 1712.84,6020.91 r90 top value=0
R368 "0201, 0 Ohm" "RES, R0201, Height 0.23mm" 1688.35,6020.7 r90 top value=0
R369 "0201, 0 Ohm" "RES, R0201, Height 0.23mm" 6808.38,808.66 r0 top value=0
R370 "0201, 0 Ohm" "RES, R0201, Height 0.23mm" 6808.38,833.59 r0 top value=0
R371 "0201, 10k, 5%" "RES, R0201, Height 0.23mm" 6959.63,645.34 r270 bottom value=10k
R372 "0201, 10k, 5%" "RES, R0201, Height 0.23mm" 6934.29,645.34 r270 bottom value=10k
R373 "0201, 10k, 5%" "RES, R0201, Height 0.23mm" 1737.13,6157.88 r180 bottom value=10k
R374 "0201, 10k, 5%" "RES, R0201, Height 0.23mm" 1737.13,6132.41 r180 bottom value=10k
R375 "0201, 10k, 5%" "RES, R0201, Height 0.23mm" 1870.37,6159.56 r0 bottom value=10k
R376 "0201, 10k, 5%" "RES, R0201, Height 0.23mm" 1870.67,6133.87 r0 bottom value=10k
R377 "0201, 200k, 1%" "RES, R0201, Height 0.23mm" 6516.1,104.56 r0 bottom value=200k
R378 "0201, 200k, 1%" "RES, R0201, Height 0.23mm" 6997.38,1596 r90 bottom value=200k
R379 "0201, 0 Ohm" "RES, R0201, Height 0.23mm" 6808.84,1596 r0 top value=0
R380 "0201, 0 Ohm" "RES, R0201, Height 0.23mm" 6808.67,1620.58 r0 top value=0
R381 "0201, 0 Ohm" "RES, R0201, Height 0.23mm" 6515.2,279.22 r270 top value=0
R382 "0201, 0 Ohm" "RES, R0201, Height 0.23mm" 6539.01,279.25 r270 top value=0
R383 "0201, 10k, 5%" "RES, R0201, Height 0.23mm" 6492.13,130.84 r0 bottom value=10k
R384 "0201, 10k, 5%" "RES, R0201, Height 0.23mm" 6492.13,155.85 r0 bottom value=10k
R385 "0201, 10k, 5%" "RES, R0201, Height 0.23mm" 6971.83,1570.8 r90 bottom value=10k
R386 "0201, 10k, 5%" "RES, R0201, Height 0.23mm" 6946.07,1570.8 r90 bottom value=10k
R387 "0201, 10k, 5%" "RES, R0201, Height 0.23mm" 6357.95,131.26 r180 bottom value=10k
R388 "0201, 10k, 5%" "RES, R0201, Height 0.23mm" 6357.77,156.78 r180 bottom value=10k
R389 "0201, 10k, 5%" "RES, R0201, Height 0.23mm" 6965.54,1435.4 r270 bottom value=10k
R390 "0201, 10k, 5%" "RES, R0201, Height 0.23mm" 6940.39,1435.54 r270 bottom value=10k
R391 "0201, 10k, 5%" "RES, R0201, Height 0.23mm" 5966.11,4634 r90 top value=10k
R392 "0201, 10k, 5%" "RES, R0201, Height 0.23mm" 6031.69,4903.55 r180 top value=10k
R393 "0201, 49.9k, 1%" "RES, R0201, Height 0.23mm" 6003.08,5088.97 r270 top value=49.9k
R394 "0201, 2.2K, 5%" "RES, R0201, Height 0.23mm" 2064.26,5983.29 r180 bottom value=2.2k
R395 "0201, 10k, 5%" "RES, R0201, Height 0.23mm" 6335.8,5326.47 r180 bottom value=10k
R396 "0201, 49.9k, 1%" "RES, R0201, Height 0.23mm" 5978.19,5088.97 r270 top value=49.9k
R397 "0201, 10k, 5%" "RES, R0201, Height 0.23mm" 4095.39,4942.85 r90 bottom value=10k
R398 "0201, 10k, 5%" "RES, R0201, Height 0.23mm" 4389.89,5000.1 r90 bottom value=10k
R399 "0201, 2.2K, 5%" "RES, R0201, Height 0.23mm" 2064.26,5955.97 r180 bottom value=2.2k
R400 "0201, 10k, 5%" "RES, R0201, Height 0.23mm" 2004.56,6008.77 r0 bottom value=10k
R401 "0201, 0 Ohm" "RES, R0201, Height 0.23mm" 3745.23,5768.04 r270 top value=0
R402 "0201, 0 Ohm" "RES, R0201, Height 0.23mm" 5148.36,5503.58 r180 bottom value=0
R403 "0201, 0 Ohm" "RES, R0201, Height 0.23mm" 5148.46,5529.42 r180 bottom value=0
R404 "0201, 0 Ohm" "RES, R0201, Height 0.23mm" 5183.08,5495.56 r90 bottom value=0
R405 "0201, 0 Ohm" "RES, R0201, Height 0.23mm" 5183.1,5538.57 r270 bottom value=0
R406 "0201, 49.9k, 1%" "RES, R0201, Height 0.23mm" 5936.22,5029.83 r0 top value=49.9k
R407 "0201, 49.9k, 1%" "RES, R0201, Height 0.23mm" 5936.37,5004.45 r0 top value=49.9k
R408 "0402, 1.2k, 1%" "RES, R0402, RF" 916.86,5736 r270 top value=1.2k
R409 "0201, 49.9k, 1%" "RES, R0201, Height 0.23mm" 5513.08,3640.45 r180 top value=49.9k
R410 "0402, 100k, 1%" "RES, R0402, RF" 834.48,5649.37 r180 top value=100k
R411 "0201, 0 Ohm" "RES, R0201, Height 0.23mm" 2005.6,5982.48 r180 bottom value=0
R412 "0201, 49.9k, 1%" "RES, R0201, Height 0.23mm" 5936.51,4979.07 r0 top value=49.9k
R413 "0402, 1.0k, 5%" "RES, R0402, RF" 6658.77,3002.13 r0 top value=1.0k
R414 "0402, 1.0k, 5%" "RES, R0402, RF" 6658.77,2827.31 r0 top value=1.0k
R415 "0402, 0 Ohm" "RES, R0402, RF" 405.42,5735.8 r270 bottom value=0
R416 "0201, 10k, 5%" "RES, R0201, Height 0.23mm" 5658.23,3045.42 r90 bottom value=10k
R417 "0201, 47k, 1%" "RES, R0201, Height 0.23mm" 2061.15,1454.32 r90 bottom value=47k
R418 "0402, 0 Ohm" "RES, R0402, RF" 5169.61,1159.6 r90 top value=0
R419 "0402, 0 Ohm" "RES, R0402, RF" 5139.83,1159.54 r90 top value=0
R420 "0201, 47k, 1%" "RES, R0201, Height 0.23mm" 6104.05,4690.86 r0 top value=47k
R421 "0201, 47k, 1%" "RES, R0201, Height 0.23mm" 6112.54,4782.43 r90 top value=47k
R422 "0201, 47k, 1%" "RES, R0201, Height 0.23mm" 5923.65,4808.66 r270 top value=47k
R423 "0201, 47k, 1%" "RES, R0201, Height 0.23mm" 5891.22,4719.33 r270 top value=47k
R424 "0201, 47k, 1%" "RES, R0201, Height 0.23mm" 6408.29,4906.15 r90 top value=47k
R425 "0201, 0 Ohm" "RES, R0201, Height 0.23mm" 5864.79,2939.03 r180 bottom value=0
R426 "0201, 49.9k, 1%" "RES, R0201, Height 0.23mm" 5864.79,2991.19 r180 bottom value=49.9k
R427 "0201, 10k, 5%" "RES, R0201, Height 0.23mm" 1680.09,4849.93 r180 top value=10k
R428 "0201, 4.7k, 5%" "RES, R0201, Height 0.23mm" 5613.69,2353.77 r0 bottom value=4.7k
R429 "0201, 1.0k, 5%" "RES, R0201, Height 0.23mm" 4184.13,3946.81 r90 bottom value=1.0k
R430 "0201, 1.0k, 5%" "RES, R0201, Height 0.23mm" 4120.8,3946.81 r90 bottom value=1.0k
R431 "0201, 0 Ohm" "RES, R0201, Height 0.23mm" 5409.07,2830.97 r0 bottom value=0
R432 "0402, 0 Ohm" "RES, R0402, RF" 5337.23,2584.14 r0 bottom value=0
R433 "0201, 1.0k, 5%" "RES, R0201, Height 0.23mm" 4146.05,3946.81 r90 bottom value=1.0k
R434 "0201, 49.9k, 1%" "RES, R0201, Height 0.23mm" 5340.93,2642.16 r0 bottom value=49.9k
R435 "0201, 2.2K, 5%" "RES, R0201, Height 0.23mm" 1800.79,1650.82 r180 top value=2.2k
R436 "0201, 2.2K, 5%" "RES, R0201, Height 0.23mm" 1800.79,1676.84 r180 top value=2.2k
R437 "0201, 10k, 5%" "RES, R0201, Height 0.23mm" 1937.66,1657.22 r270 top value=10k
R440 "0201, 0 Ohm" "RES, R0201, Height 0.23mm" 5613.69,2379.21 r180 bottom value=0
R441 "0201, 100k, 5%" "RES, R0201, Height 0.23mm" 3471.87,909.44 r180 bottom value=100k
R442 "0201, 47k, 1%" "RES, R0201, Height 0.23mm" 6408.26,4732.7 r90 top value=47k
R443 "0201, 0 Ohm" "RES, R0201, Height 0.23mm" 5854.49,2904.61 r90 bottom value=0
R444 "0201, 10k, 5%" "RES, R0201, Height 0.23mm" 5258.89,3991.39 r90 bottom value=10k
R445 "0201, 10k, 5%" "RES, R0201, Height 0.23mm" 5284.73,3991.39 r90 bottom value=10k
R446 "0201, 10k, 5%" "RES, R0201, Height 0.23mm" 5310.57,3991.39 r90 bottom value=10k
R447 "0201, 10k, 5%" "RES, R0201, Height 0.23mm" 5336.41,3991.39 r90 bottom value=10k
R448 "0201, 10k, 5%" "RES, R0201, Height 0.23mm" 6114.83,4001.77 r90 bottom value=10k
R449 "0201, 10k, 5%" "RES, R0201, Height 0.23mm" 6140.4,4001.8 r90 bottom value=10k
R450 "0201, 47k, 1%" "RES, R0201, Height 0.23mm" 6408.18,4670.15 r270 top value=47k
R451 "0402, 15k, 5%" "RES, R0402, RF" 1132.09,1878.86 r0 bottom value=15k
R452 "0201, 2.2K, 5%" "RES, R0201, Height 0.23mm" 1703.51,5984.34 r0 bottom value=2.2k
R453 "0201, 2.2K, 5%" "RES, R0201, Height 0.23mm" 1703.3,5958.85 r0 bottom value=2.2k
R454 "0201, 2.2K, 5%" "RES, R0201, Height 0.23mm" 6775.34,1609.34 r270 bottom value=2.2k
R455 "0201, 2.2K, 5%" "RES, R0201, Height 0.23mm" 6749.68,1609.34 r270 bottom value=2.2k
R456 "0201, 2.2K, 5%" "RES, R0201, Height 0.23mm" 6774.29,824.5 r270 bottom value=2.2k
R457 "0201, 2.2K, 5%" "RES, R0201, Height 0.23mm" 6748.76,824.68 r270 bottom value=2.2k
R458 "0201, 2.2K, 5%" "RES, R0201, Height 0.23mm" 6530.02,312.85 r180 bottom value=2.2k
R459 "0201, 2.2K, 5%" "RES, R0201, Height 0.23mm" 6530.02,338.28 r180 bottom value=2.2k
R460 "0201, 2.2K, 5%" "RES, R0201, Height 0.23mm" 2334.76,5683.86 r180 bottom value=2.2k
R461 "0201, 2.2K, 5%" "RES, R0201, Height 0.23mm" 2334.76,5605.46 r180 bottom value=2.2k
R462 "0201, 0 Ohm" "RES, R0201, Height 0.23mm" 2005.74,5955.06 r180 bottom value=0
R463 "0201, 2.2K, 5%" "RES, R0201, Height 0.23mm" 6777.31,1256.76 r90 bottom value=2.2k
R464 "0201, 2.2K, 5%" "RES, R0201, Height 0.23mm" 6751.38,1256.76 r90 bottom value=2.2k
R465 "0201, 10k, 5%" "RES, R0201, Height 0.23mm" 6803.53,1313.38 r270 bottom value=10k
R466 "0201, 10k, 5%" "RES, R0201, Height 0.23mm" 2075.56,5563.67 r270 bottom value=10k
R467 "0201, 0 Ohm" "RES, R0201, Height 0.23mm" 6777.57,1313.33 r90 bottom value=0
R468 "0201, 0 Ohm" "RES, R0201, Height 0.23mm" 1926.38,5607.2 r180 bottom value=0
R469 "0201, 0 Ohm" "RES, R0201, Height 0.23mm" 1926.38,5632.35 r180 bottom value=0
R470 "0201, 0 Ohm" "RES, R0201, Height 0.23mm" 1961.1,5597.83 r90 bottom value=0
R471 "0201, 0 Ohm" "RES, R0201, Height 0.23mm" 1961.1,5640.78 r270 bottom value=0
R472 "0201, 10k, 5%" "RES, R0201, Height 0.23mm" 2554.1,1509.29 r270 top value=10k
R473 "0201, 10k, 5%" "RES, R0201, Height 0.23mm" 2619.51,1509.29 r270 top value=10k
R474 "0201, 10k, 5%" "RES, R0201, Height 0.23mm" 2684.92,1509.29 r270 top value=10k
R475 "0201, 1.0k, 5%" "RES, R0201, Height 0.23mm" 2587.09,1500.49 r180 top value=1.0k
R476 "0201, 1.0k, 5%" "RES, R0201, Height 0.23mm" 2652.67,1500.49 r180 top value=1.0k
R477 "0201, 1.0k, 5%" "RES, R0201, Height 0.23mm" 2719.14,1500.85 r180 top value=1.0k
R478 "0201, 0 Ohm" "RES, R0201, Height 0.23mm" 6751.62,1313.43 r90 bottom value=0
R479 "0201, 0 Ohm" "RES, R0201, Height 0.23mm" 2291.86,5631.7 r180 bottom value=0
R480 "0201, 0 Ohm" "RES, R0201, Height 0.23mm" 2291.94,5658.15 r180 bottom value=0
R481 "0201, 2.2K, 5%" "RES, R0201, Height 0.23mm" 6775.03,463.09 r90 bottom value=2.2k
R482 "0201, 2.2K, 5%" "RES, R0201, Height 0.23mm" 6749.04,463.44 r90 bottom value=2.2k
R483 "0201, 10k, 5%" "RES, R0201, Height 0.23mm" 6800.12,519.08 r270 bottom value=10k
R484 "0201, 0 Ohm" "RES, R0201, Height 0.23mm" 6774.32,519.08 r90 bottom value=0
R485 "0201, 0 Ohm" "RES, R0201, Height 0.23mm" 6748.41,519.08 r90 bottom value=0
R486 "0201, 2.2K, 5%" "RES, R0201, Height 0.23mm" 6171.73,312.75 r0 bottom value=2.2k
R487 "0201, 2.2K, 5%" "RES, R0201, Height 0.23mm" 6171.65,338.69 r0 bottom value=2.2k
R488 "0201, 10k, 5%" "RES, R0201, Height 0.23mm" 6231.16,287.33 r180 bottom value=10k
R489 "0201, 0 Ohm" "RES, R0201, Height 0.23mm" 6231.18,313.38 r0 bottom value=0
R490 "0201, 0 Ohm" "RES, R0201, Height 0.23mm" 6231.11,339.18 r0 bottom value=0
R491 "0201, 4.7k, 5%" "RES, R0201, Height 0.23mm" 4229,161.63 r0 bottom value=4.7k
R492 "0201, 4.7k, 5%" "RES, R0201, Height 0.23mm" 4229,136.25 r0 bottom value=4.7k
R493 "0201, 0 Ohm" "RES, R0201, Height 0.23mm" 4520.04,165.77 r180 bottom value=0
R494 "0201, 0 Ohm" "RES, R0201, Height 0.23mm" 4520.04,140.4 r180 bottom value=0
R495 "0201, 4.7k, 5%" "RES, R0201, Height 0.23mm" 5242.33,6081.59 r270 bottom value=4.7k
R496 "0201, 4.7k, 5%" "RES, R0201, Height 0.23mm" 5216.35,6081.59 r270 bottom value=4.7k
R497 "0201, 10k, 5%" "RES, R0201, Height 0.23mm" 5270.49,5786.18 r270 bottom value=10k
R498 "0201, 0 Ohm" "RES, R0201, Height 0.23mm" 5244.31,5786.61 r90 bottom value=0
R499 "0201, 0 Ohm" "RES, R0201, Height 0.23mm" 5218.49,5786.5 r90 bottom value=0
R500 "0201, 4.7k, 5%" "RES, R0201, Height 0.23mm" 6147.98,5879.31 r180 bottom value=4.7k
R501 "0201, 4.7k, 5%" "RES, R0201, Height 0.23mm" 6147.84,5905 r180 bottom value=4.7k
R502 "0201, 10k, 5%" "RES, R0201, Height 0.23mm" 5849.79,5851.81 r180 bottom value=10k
R503 "0201, 0 Ohm" "RES, R0201, Height 0.23mm" 5849.87,5877.71 r0 bottom value=0
R504 "0201, 0 Ohm" "RES, R0201, Height 0.23mm" 5849.87,5903.79 r0 bottom value=0
R505 "0201, 4.7k, 5%" "RES, R0201, Height 0.23mm" 382.43,2945.49 r270 bottom value=4.7k
R506 "0201, 4.7k, 5%" "RES, R0201, Height 0.23mm" 356.68,2945.64 r270 bottom value=4.7k
R507 "0201, 10k, 5%" "RES, R0201, Height 0.23mm" 409.32,2648.7 r270 bottom value=10k
R508 "0201, 0 Ohm" "RES, R0201, Height 0.23mm" 383,2648.7 r90 bottom value=0
R509 "0201, 0 Ohm" "RES, R0201, Height 0.23mm" 356.73,2648.66 r90 bottom value=0
R510 "0201, 0 Ohm" "RES, R0201, Height 0.23mm" 1302.4,6032.01 r0 bottom value=0
R511 "0201, 0 Ohm" "RES, R0201, Height 0.23mm" 2334.76,5658.2 r180 bottom value=0
R512 "0201, 0 Ohm" "RES, R0201, Height 0.23mm" 2334.76,5631.45 r180 bottom value=0
R513 "0201, 0 Ohm" "RES, R0201, Height 0.23mm" 5667.18,5582.21 r180 top value=0
R514 "0201, 0 Ohm" "RES, R0201, Height 0.23mm" 5667.18,5494.63 r180 top value=0
R515 "0201, 10k, 5%" "RES, R0201, Height 0.23mm" 5271.89,3846.13 r270 bottom value=10k
R516 "0201, 10k, 5%" "RES, R0201, Height 0.23mm" 5243.19,3856.06 r270 bottom value=10k
R517 "0201, 0 Ohm" "RES, R0201, Height 0.23mm" 1163.83,6108.41 r90 bottom value=0
R518 "0201, 10k, 5%" "RES, R0201, Height 0.23mm" 1792.39,1790.33 r90 top value=10k
R519 "0201, 200k, 1%" "RES, R0201, Height 0.23mm" 3652.52,1240.05 r180 bottom value=200k
R520 "0201, 2.2K, 5%" "RES, R0201, Height 0.23mm" 3671.6,1210.09 r0 bottom value=2.2k
R521 "0201, 2.2K, 5%" "RES, R0201, Height 0.23mm" 3672.07,1185.32 r0 bottom value=2.2k
R522 "0201, 10k, 5%" "RES, R0201, Height 0.23mm" 3819.16,1217.17 r0 bottom value=10k
R523 "0201, 10k, 5%" "RES, R0201, Height 0.23mm" 3819.16,1191.88 r0 bottom value=10k
R524 "0201, 432k, 1%" "RES, R0201, Height 0.23mm" 1234.63,1786.1 r180 bottom value=432k
R525 "0402, 4.87k, 1%" "RES, R0402, RF" 1469.41,738.96 r180 bottom value=4.87k
R526 "0402, 0 Ohm" "RES, R0402, RF" 6310.81,5408.02 r0 bottom value=0
R527 "0201, 47k, 1%" "RES, R0201, Height 0.23mm" 6408.93,4994.16 r90 top value=47k
R528 "0201, 49.9k, 1%" "RES, R0201, Height 0.23mm" 5936.32,4954.06 r0 top value=49.9k
R529 "0201, 47k, 1%" "RES, R0201, Height 0.23mm" 6408.81,4951.85 r90 top value=47k
R530 "0402, 0 Ohm" "RES, R0402, RF" 6322.36,5453.41 r270 bottom value=0
R531 "0402, 1.2k, 1%" "RES, R0402, RF" 2091.5,1461.32 r90 bottom value=1.2k
R532 "0201, 47k, 1%" "RES, R0201, Height 0.23mm" 6122.95,4945 r270 top value=47k
R533 "0201, 2.2K, 5%" "RES, R0201, Height 0.23mm" 6674.43,3040.86 r270 top value=2.2k
R534 "0201, 2.2K, 5%" "RES, R0201, Height 0.23mm" 6673.2,2867.13 r270 top value=2.2k
R535 "0201, 2.2K, 5%" "RES, R0201, Height 0.23mm" 792.06,6190.52 r270 bottom value=2.2k
R536 "0402, 1.0k, 5%" "RES, R0402, RF" 792.3,6139.94 r90 bottom value=1.0k
R537 "0402, 0 Ohm" "RES, R0402, RF" 1624.86,5045.69 r0 top value=0
R538 "0201, 10k, 5%" "RES, R0201, Height 0.23mm" 6361.18,5403.53 r180 bottom value=10k
R539 "0201, 10k, 5%" "RES, R0201, Height 0.23mm" 5527.61,2250.05 r270 bottom value=10k
R540 "0201, 10k, 5%" "RES, R0201, Height 0.23mm" 5466.91,2250.88 r270 bottom value=10k
R541 "0201, 10k, 5%" "RES, R0201, Height 0.23mm" 5441.45,2275.78 r270 bottom value=10k
R542 "0201, 10k, 5%" "RES, R0201, Height 0.23mm" 5415.85,2275.98 r270 bottom value=10k
R543 "0201, 10k, 5%" "RES, R0201, Height 0.23mm" 5343.09,2356.03 r180 bottom value=10k
R544 "0201, 10k, 5%" "RES, R0201, Height 0.23mm" 5343.09,2381.4 r180 bottom value=10k
R545 "0201, 10k, 5%" "RES, R0201, Height 0.23mm" 5343.09,2406.77 r180 bottom value=10k
R546 "0201, 10k, 5%" "RES, R0201, Height 0.23mm" 5343.09,2432.14 r180 bottom value=10k
R547 "0201, 100k, 5%" "RES, R0201, Height 0.23mm" 5518.76,2283.94 r0 bottom value=100k
R548 "0201, 100k, 5%" "RES, R0201, Height 0.23mm" 5475.68,2283.94 r180 bottom value=100k
R549 "0201, 100k, 5%" "RES, R0201, Height 0.23mm" 5457,2334.74 r270 top value=100k
R550 "0201, 100k, 5%" "RES, R0201, Height 0.23mm" 5431.51,2334.82 r270 top value=100k
R551 "0201, 100k, 5%" "RES, R0201, Height 0.23mm" 5411.67,2368.12 r180 top value=100k
R552 "0201, 100k, 5%" "RES, R0201, Height 0.23mm" 5411.67,2393.18 r180 top value=100k
R553 "0201, 100k, 5%" "RES, R0201, Height 0.23mm" 5411.67,2417.81 r180 top value=100k
R554 "0201, 100k, 5%" "RES, R0201, Height 0.23mm" 5411.67,2442.87 r180 top value=100k
R555 "0201, 0 Ohm" "RES, R0201, Height 0.23mm" 1352.1,93.34 r0 bottom value=0
R556 "0201, 0 Ohm" "RES, R0201, Height 0.23mm" 1506.57,107.1 r90 bottom value=0
R557 "0201, 1.0k, 5%" "RES, R0201, Height 0.23mm" 3726.64,370.94 r90 bottom value=1.0k
R558 "0201, 1.0k, 5%" "RES, R0201, Height 0.23mm" 3750.73,370.94 r90 bottom value=1.0k
R559 "0402, 909k, 1%" "RES, R0402, RF" 3802.01,351.44 r90 bottom value=909k
R560 "0201, 200k, 1%" "RES, R0201, Height 0.23mm" 3805.77,191.07 r0 bottom value=200k
R561 "0201, 200k, 1%" "RES, R0201, Height 0.23mm" 3837.15,293.84 r0 bottom value=200k
R562 "0201, 200k, 1%" "RES, R0201, Height 0.23mm" 3837.15,242.81 r0 bottom value=200k
R563 "0201, 200k, 1%" "RES, R0201, Height 0.23mm" 3837.15,217.24 r0 bottom value=200k
R564 "0201, 10k, 5%" "RES, R0201, Height 0.23mm" 3718.6,336.35 r0 bottom value=10k
R565 "0201, 10k, 5%" "RES, R0201, Height 0.23mm" 3760.86,336.35 r180 bottom value=10k
R566 "0201, 1.0k, 5%" "RES, R0201, Height 0.23mm" 3837.15,268.79 r180 bottom value=1.0k
R567 "0201, 0 Ohm" "RES, R0201, Height 0.23mm" 3752.9,181.44 r90 bottom value=0
R568 "0201, 5.1k, 1%" "RES, R0201, Height 0.23mm" 3691.17,6063.05 r0 bottom value=5.1k
R569 "0201, 5.1k, 1%" "RES, R0201, Height 0.23mm" 3778.99,5847.88 r180 top value=5.1k
R570 "0201, 10k, 5%" "RES, R0201, Height 0.23mm" 1577.21,3852.55 r0 bottom value=10k
R571 "0201, 10k, 5%" "RES, R0201, Height 0.23mm" 1436.43,5216.94 r0 bottom value=10k
R572 "0402, 220k, 1%" "RES, R0402, RF" 5940.25,694.9 r0 bottom value=220k
R573 "0201, 0 Ohm" "RES, R0201, Height 0.23mm" 5832.86,740.71 r270 bottom value=0
R574 "0402, 30.1k, 1%" "RES, R0402, RF" 5928.66,741.22 r270 bottom value=30.1k
R575 "0201, 0 Ohm" "RES, R0201, Height 0.23mm" 2318.21,6071.74 r0 bottom value=0
R576 "0201, 0 Ohm" "RES, R0201, Height 0.23mm" 6834.86,967.56 r180 bottom value=0
R577 "0201, 0 Ohm" "RES, R0201, Height 0.23mm" 2247.45,5849.72 r270 bottom value=0
R578 "0201, 49.9k, 1%" "RES, R0201, Height 0.23mm" 2281.78,5866.84 r180 bottom value=49.9k
R579 "0201, 0 Ohm" "RES, R0201, Height 0.23mm" 6921.76,1179.73 r90 bottom value=0
R580 "0201, 49.9k, 1%" "RES, R0201, Height 0.23mm" 6887.41,1162.95 r0 bottom value=49.9k
R581 "0201, 0 Ohm" "RES, R0201, Height 0.23mm" 2152.54,5865.61 r180 bottom value=0
R582 "0201, 0 Ohm" "RES, R0201, Height 0.23mm" 7017.36,1171.38 r0 bottom value=0
R583 "0201, 0 Ohm" "RES, R0201, Height 0.23mm" 2203.37,6121.5 r0 bottom value=0
R584 "0201, 49.9k, 1%" "RES, R0201, Height 0.23mm" 2203.24,6069.44 r0 bottom value=49.9k
R585 "0201, 0 Ohm" "RES, R0201, Height 0.23mm" 6953.32,919.84 r0 bottom value=0
R586 "0201, 49.9k, 1%" "RES, R0201, Height 0.23mm" 6953.32,970.82 r0 bottom value=49.9k
R587 "0201, 0 Ohm" "RES, R0201, Height 0.23mm" 5957.59,224.12 r180 bottom value=0
R588 "0201, 0 Ohm" "RES, R0201, Height 0.23mm" 6835.08,1740.88 r180 bottom value=0
R589 "0201, 0 Ohm" "RES, R0201, Height 0.23mm" 6052.98,454.52 r180 bottom value=0
R590 "0201, 0 Ohm" "RES, R0201, Height 0.23mm" 6918.63,1957.17 r90 bottom value=0
R591 "0201, 49.9k, 1%" "RES, R0201, Height 0.23mm" 6009.55,428.56 r0 bottom value=49.9k
R592 "0201, 49.9k, 1%" "RES, R0201, Height 0.23mm" 6884.46,1940.87 r0 bottom value=49.9k
R593 "0201, 0 Ohm" "RES, R0201, Height 0.23mm" 7019.73,1966.65 r0 bottom value=0
R594 "0201, 0 Ohm" "RES, R0201, Height 0.23mm" 6034.01,178.18 r90 bottom value=0
R595 "0201, 0 Ohm" "RES, R0201, Height 0.23mm" 6961.54,1716.89 r0 bottom value=0
R596 "0201, 0 Ohm" "RES, R0201, Height 0.23mm" 6289.71,121.02 r180 bottom value=0
R597 "0201, 49.9k, 1%" "RES, R0201, Height 0.23mm" 6961.54,1767.24 r0 bottom value=49.9k
R598 "0201, 49.9k, 1%" "RES, R0201, Height 0.23mm" 6229.63,129.96 r270 bottom value=49.9k
R599 "0402, 4.87k, 1%" "RES, R0402, RF" 2153.2,136.29 r180 bottom value=4.87k
R600 "0402, 68.1k, 1%" "RES, R0402, RF" 1461.18,906.79 r90 bottom value=68.1k
R601 "0402, 68.1k, 1%" "RES, R0402, RF" 2144.05,289.96 r90 bottom value=68.1k
R602 "0402, 3.0k, 5%" "RES, R0402, RF" 1446.37,861.1 r0 bottom value=3.0k
R603 "0603, 10k, 5%" "RES, R0603, RF" 1582.12,943.61 r90 bottom value=10k
R604 "0402, 8.2k, 5%" "RES, R0402, RF" 2128.74,243.71 r0 bottom value=8.2k
R605 "0603, 10k, 5%" "RES, R0603, RF" 2264.03,334.9 r90 bottom value=10k
R606 "0201, 10k, 5%" "RES, R0201, Height 0.23mm" 6056.93,3796.05 r0 bottom value=10k
R607 "0201, 0 Ohm" "RES, R0201, Height 0.23mm" 2923.38,3554.6 r90 bottom value=0
R608 "0201, 0 Ohm" "RES, R0201, Height 0.23mm" 2894.83,3554.58 r90 bottom value=0
S1 "E-Switch, 500ASSP1M2QE" "E-Switch, 500ASSP1M2QE" 1870,1037.62 r270 top value=500ASSP1M2QE
S2 "EW-Switch, BTS-1101NE-2-BB-RP-K" "EW-Switch, BTS-1101NE-2-BB-RP-K" 250.35,5373.93 r0 top value=BTS-1101NE-2-BB-RP-K
S3 "EW-Switch, BTS-1101NE-2-BB-RP-K" "EW-Switch, BTS-1101NE-2-BB-RP-K" 576.97,6177.92 r180 top value=BTS-1101NE-2-BB-RP-K
S5 "EW-Switch, BTS-1101NE-2-BB-RP-K" "EW-Switch, BTS-1101NE-2-BB-RP-K" 6881.87,3002.66 r0 top value=BTS-1101NE-2-BB-RP-K
S6 "EW-Switch, BTS-1101NE-2-BB-RP-K" "EW-Switch, BTS-1101NE-2-BB-RP-K" 6881.87,2830.18 r180 top value=BTS-1101NE-2-BB-RP-K
S7 "Diptronics, DJR-04-T-V" "Diptronics, DJR-04-T-V" 1609.27,3018.66 r90 top value=DJR-04-T-V
S8 "EW-Switch, BTS-1101NE-2-BB-RP-K" "EW-Switch, BTS-1101NE-2-BB-RP-K" 250.81,5724.88 r0 top value=BTS-1101NE-2-BB-RP-K
SB1 "Solderbridge Closed" "Solder Bridge Closed" 4394.8,1232.7 r90 top net-tie
SB2 "Solderbridge Closed" "Solder Bridge Closed" 5968.35,5971.26 r180 top net-tie
SB3 "Solderbridge Open" "Solder Bridge Open" 4323.6,4790.84 r270 top
SB4 "Solderbridge Closed" "Solder Bridge Closed" 820.44,5591.05 r90 top net-tie
SB5 "Solderbridge Closed" "Solder Bridge Closed" 5601.28,5582.52 r180 top net-tie
SB6 "Solderbridge Closed" "Solder Bridge Closed" 5601.28,5494.41 r180 top net-tie
TP1 "Test Point" "Test Point, SMT 1mm Round" 2223.94,977.18 r90 top
TP2 "Test Point" "Test Point, SMT 1mm Round" 3080.93,337.74 r270 top
TP3 "Test Point" "Test Point, SMT 1mm Round" 2877.02,1067.53 r90 top
TP4 "Test Point" "Test Point, SMT 1mm Round" 1215.72,231.01 r180 top
TP5 "Test Point" "Test Point, SMT 1mm Round" 1790.11,281.46 r180 top
TP6 "Test Point" "Test Point, SMT 1mm Round" 1392.35,924.63 r0 top
TP7 "Test Point" "Test Point, SMT 1mm Round" 1812.65,611.12 r180 top
TP8 "Test Point" "Test Point, SMT 1mm Round" 510.2,685.12 r90 top
TP9 "Test Point, with test ring, TH" "Test Point, TH 1mm Round with test ring, Red" 2028.72,327.34 r180 top
TP10 "Test Point" "Test Point, SMT 20mil Round" 1464.59,3760.08 r0 top
TP11 "Test Point" "Test Point, SMT 20mil Round" 1355.7,3304.1 r90 top
TP12 "Test Point" "Test Point, SMT 20mil Round" 1425.73,3760.08 r0 top
TP13 "Test Point" "Test Point, SMT 20mil Round" 1185.58,3317.34 r90 top
TP14 "Test Point" "Test Point, SMT 20mil Round" 1468.53,4944.37 r0 top
TP15 "Test Point" "Test Point, SMT 20mil Round" 1359.64,4486.41 r90 top
TP16 "Test Point" "Test Point, SMT 20mil Round" 1429.68,4944.37 r0 top
TP17 "Test Point" "Test Point, SMT 20mil Round" 1189.52,4499.65 r90 top
TP20 "Test Point" "Test Point, SMT 1mm Round" 3287.29,3779.59 r180 bottom
TP21 "Test Point" "Test Point, SMT 1mm Round" 4455.04,2639.06 r180 bottom
TP22 "Test Point" "Test Point, SMT 1mm Round" 6390.72,4604.06 r0 bottom
TP23 "Test Point" "Test Point, SMT 1mm Round" 2823.65,2640.09 r180 bottom
TP24 "Test Point" "Test Point, SMT 1mm Round" 1382.33,4269.71 r270 top
TP25 "Test Point" "Test Point, SMT 1mm Round" 4401.31,3920.19 r90 bottom
TP26 "Test Point" "Test Point, SMT 1mm Round" 3685.77,151.91 r90 bottom
TP29 "Test Point" "Test Point, SMT 20mil Round" 4124.21,4954.34 r180 bottom
TP30 "Test Point" "Test Point, SMT 20mil Round" 4348.31,4963.64 r180 bottom
TP31 "Test Point" "Test Point, SMT 20mil Round" 4368.31,5038.35 r180 bottom
TP33 "Test Point" "Test Point, SMT 20mil Round" 4277.21,4991.99 r180 bottom
TP34 "Test Point" "Test Point, SMT 1mm Round" 4104.75,2638.37 r180 bottom
TP35 "Test Point" "Test Point, SMT 1mm Round" 2739.96,2640.09 r180 bottom
TP36 "Test Point" "Test Point, SMT 1mm Round" 3366.17,3779.59 r180 bottom
TP37 "Test Point" "Test Point, SMT 1mm Round" 4100.65,2486.2 r180 bottom
TP38 "Test Point" "Test Point, SMT 1mm Round" 4260.66,3593.3 r180 bottom
TP39 "Test Point" "Test Point, SMT 1mm Round" 3480.55,960.58 r90 bottom
TP40 "Test Point" "Test Point, SMT 1mm Round" 1443.78,1678.08 r90 bottom
TP41 "Test Point, with test ring, TH" "Test Point, TH 1mm Round with test ring, Green" 6081.7,1904.99 r0 top
TP42 "Test Point, with test ring, TH" "Test Point, TH 1mm Round with test ring, Green" 176.61,1760.75 r180 top
TP43 "Test Point, with test ring, TH" "Test Point, TH 1mm Round with test ring, Green" 4875.49,5765.8 r180 top
U1 "TI, TPS65263RHBR" "QFN32, 5x5, Pitch 0.5mm, Height 1mm" 2535.26,489.75 r90 top value=TPS65263RHBR
U2 "TI, INA232AIDDFR" "SOT23_8, Height 1.1mm" 3212.28,625.37 r0 bottom value=INA232AIDDFR
U3 "TI, INA232AIDDFR" "SOT23_8, Height 1.1mm" 2056.57,1227.36 r180 top value=INA232AIDDFR
U4 "TI, TPS65400QRGZTQ1" "QFN48, 7x7, Pitch 0.5mm, Height 1.0mm" 1356.68,1736.88 r90 top value=TPS65400QRGZTQ1
U5 "TI, SN74AUP1G125DSFR" "X2SON, Height 0.4mm" 3810.06,52.19 r270 bottom value=SN74AUP1G125DSFR
U6 "TI, SN74AUP1G125DSFR" "X2SON, Height 0.4mm" 2563.76,6215.21 r90 bottom value=SN74AUP1G125DSFR
U7 "TI, TPS25751DREFR" "WQFN40, 6x4, Pitch 0.4mm, Height 0.8mm, SMD" 682.85,1125.87 r90 top locked value=TPS25751DREFR
U8 "ON Semi, CAT24C512WI-GT3" SOIC-8 1019.22,1047.14 r90 top value=CAT24C512WI-GT3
